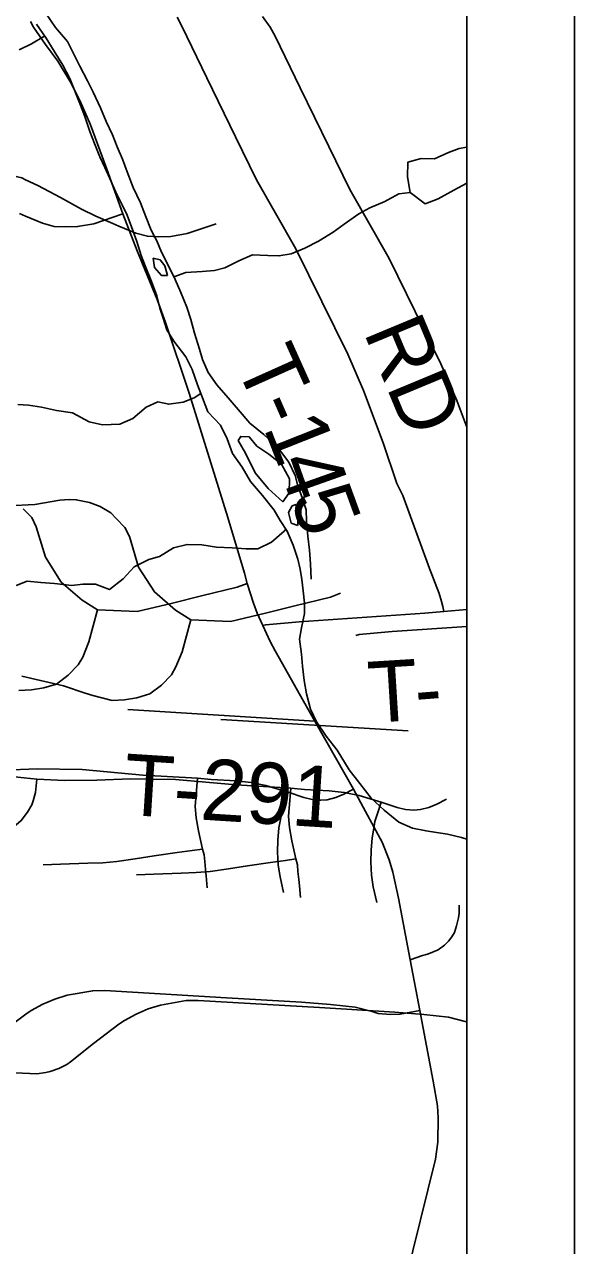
# Model space of a CAD drawing. Extents: x -38.2 to 41.9, y -4 to 24.9.
# Drawn here: x 8.49 to 9, y 18.257 to 19.391 of the extents above; entities that cross this region are included whole.
import ezdxf

# ---------------------------------------------------------------- set-up
doc = ezdxf.new("R2010")
doc.units = 0
for name, color, linetype in [('GM_X_Interchange_Ramps', 7, 'Continuous'), ('GM_X_Major_River', 7, 'Continuous'), ('GM_X_Minor_Lake', 7, 'Continuous'), ('GM_X_Minor_River', 7, 'Continuous'), ('GM_X_State_Location', 7, 'Continuous'), ('GM_X_State_Route', 7, 'Continuous'), ('GM_X_Township_Road', 7, 'Continuous'), ('GM_X_Township_Road_Text', 7, 'Continuous'), ('SH_Cut_Line', 7, 'Continuous'), ('SH_Data', 7, 'Continuous')]:
    doc.layers.add(name, color=color, linetype=linetype)

msp = doc.modelspace()

# ---------------------------------------------------------------- linework, layer by layer
at = {"layer": 'GM_X_Interchange_Ramps'}
for points in [[(5.6874, 16.3954), (5.9853, 16.3764), (6.413, 16.3602), (6.4263, 16.3595), (7.1336, 16.3198), (7.3442, 16.3107), (7.5793, 16.2961), (7.6901, 16.2894), (7.9696, 16.2752), (8.9, 16.2272), (8.9, 17.7063), (8.9, 17.9093), (8.9, 20.9), (5.1243, 20.9)], [(5.7739, 16.3862), (6.0718, 16.3672), (6.4995, 16.351), (6.5128, 16.3503), (7.2201, 16.3106), (7.4307, 16.3015), (7.6658, 16.2869), (7.7766, 16.2803), (8.0561, 16.266), (8.9, 16.2225), (8.9, 20.9), (5.2114, 20.9)]]:
    msp.add_lwpolyline(points, dxfattribs=at)
at = {"layer": 'GM_X_Major_River'}
for points in [[(8.7558, 18.8758), (8.7551, 18.8899), (8.754, 18.9028), (8.7526, 18.9157), (8.7512, 18.9297), (8.7509, 18.9403), (8.7475, 18.9506), (8.7434, 18.9624), (8.7408, 18.9719), (8.7349, 18.9844), (8.7243, 18.9982), (8.7119, 19.01), (8.6988, 19.0207), (8.6879, 19.0333), (8.6788, 19.044), (8.6683, 19.0562), (8.6601, 19.0676), (8.6548, 19.0798), (8.6522, 19.0893), (8.6474, 19.1041), (8.6441, 19.1167), (8.6404, 19.1284), (8.6348, 19.1418), (8.6296, 19.1539), (8.6247, 19.1642), (8.6168, 19.1794), (8.6124, 19.1897), (8.6071, 19.1996), (8.6019, 19.2129), (8.5974, 19.2251), (8.5907, 19.2395), (8.5851, 19.254), (8.5807, 19.2658), (8.5758, 19.2772), (8.5713, 19.2882), (8.5654, 19.3007), (8.5601, 19.3133), (8.5534, 19.3277), (8.5482, 19.3384), (8.5411, 19.3521), (8.5362, 19.362), (8.5295, 19.3749), (8.5186, 19.3879), (8.5092, 19.4016)], [(8.5008, 19.391), (8.5098, 19.3781), (8.5173, 19.3659), (8.5252, 19.353), (8.5319, 19.3404), (8.5375, 19.3267), (8.5416, 19.3157), (8.5457, 19.3054), (8.5502, 19.2914), (8.5546, 19.2803), (8.5595, 19.2678), (8.5643, 19.2579), (8.5688, 19.2476), (8.5744, 19.2351), (8.5804, 19.2233), (8.5849, 19.2138), (8.589, 19.2027), (8.5938, 19.1891), (8.5979, 19.1761), (8.6016, 19.1666), (8.6076, 19.1522), (8.6124, 19.1389), (8.6154, 19.1275), (8.6184, 19.118), (8.6217, 19.1073), (8.6284, 19.0967), (8.6393, 19.0822), (8.6453, 19.0704), (8.6501, 19.0563), (8.655, 19.0441), (8.6598, 19.0312)], [(8.6092, 19.1738), (8.6103, 19.1651), (8.6167, 19.1578), (8.6224, 19.1578)], [(8.6224, 19.1578), (8.6198, 19.1665), (8.6157, 19.1722), (8.6092, 19.1738)], [(8.6598, 19.0312), (8.6715, 19.0186), (8.6778, 19.0061), (8.6827, 18.9924), (8.6917, 18.9798), (8.6995, 18.9665), (8.7104, 18.9535), (8.7213, 18.9398), (8.727, 18.9303), (8.7333, 18.9204), (8.7389, 18.9074), (8.7434, 18.8945), (8.7456, 18.885), (8.7471, 18.8755), (8.7481, 18.8649), (8.7496, 18.8535), (8.7495, 18.844), (8.7468, 18.8307), (8.7448, 18.8201), (8.7466, 18.8061), (8.7477, 18.7951), (8.7491, 18.7818), (8.7513, 18.7693), (8.755, 18.7552), (8.7606, 18.7434), (8.7696, 18.7301), (8.7798, 18.7171), (8.791, 18.6988), (8.8008, 18.6862), (8.8113, 18.6725), (8.8233, 18.6614), (8.8369, 18.6503), (8.8497, 18.6446), (8.8622, 18.6422), (8.872, 18.6406), (8.8822, 18.639), (8.8951, 18.6359), (8.9, 18.6344)], [(8.7354, 18.956), (8.7355, 18.9689), (8.728, 18.9826), (8.7164, 18.9918), (8.7054, 18.9994), (8.6983, 19.0078), (8.6903, 19.0083), (8.6881, 19.0045)], [(8.6881, 19.0045), (8.6948, 18.9927), (8.7038, 18.9744), (8.7158, 18.9599), (8.7293, 18.9477), (8.7354, 18.956)], [(8.738, 18.9438), (8.7346, 18.9378), (8.7372, 18.9279), (8.7432, 18.9256)], [(8.7432, 18.9256), (8.7432, 18.9328), (8.7414, 18.945), (8.738, 18.9438)]]:
    msp.add_lwpolyline(points, dxfattribs=at)
at = {"layer": 'GM_X_Minor_Lake'}
for points in [[(8.9, 19.2769), (8.8929, 19.2755), (8.8831, 19.2717), (8.8702, 19.2661), (8.8577, 19.2664), (8.8452, 19.263)], [(8.8452, 19.263), (8.8449, 19.2492), (8.8475, 19.2346), (8.8615, 19.2243), (8.8736, 19.2289), (8.888, 19.2369), (8.9, 19.2434)]]:
    msp.add_lwpolyline(points, dxfattribs=at)
at = {"layer": 'GM_X_Minor_River'}
for points in [[(8.5084, 19.3801), (8.5076, 19.3795), (8.4962, 19.3727), (8.4849, 19.367)], [(8.6284, 19.1564), (8.6394, 19.1603), (8.6545, 19.1614), (8.6659, 19.1622), (8.6757, 19.1648), (8.6886, 19.1713), (8.7011, 19.177), (8.7154, 19.1762), (8.7257, 19.1758), (8.737, 19.1777), (8.7499, 19.183), (8.7624, 19.1895), (8.776, 19.1978), (8.7862, 19.2054), (8.7998, 19.2149), (8.81, 19.2206), (8.824, 19.2262), (8.8369, 19.2334), (8.8475, 19.2346), (8.8615, 19.2243), (8.8736, 19.2289), (8.888, 19.2369), (8.9, 19.2434)], [(8.6534, 19.0481), (8.647, 19.0442), (8.6368, 19.04), (8.6235, 19.0382), (8.6133, 19.0404), (8.6027, 19.0355), (8.5902, 19.0249), (8.5781, 19.0196), (8.5622, 19.0192), (8.5497, 19.0219), (8.5342, 19.0302), (8.5195, 19.0325), (8.5055, 19.0355), (8.4934, 19.0374), (8.4835, 19.0378)], [(8.7322, 18.9221), (8.7307, 18.9205), (8.719, 18.9103), (8.7061, 18.9039), (8.6955, 18.9039), (8.6823, 18.905), (8.6679, 18.9054), (8.6542, 18.9077), (8.6406, 18.908), (8.6281, 18.905), (8.6149, 18.897), (8.6051, 18.894), (8.5914, 18.8872), (8.5812, 18.8762), (8.5687, 18.8663), (8.5555, 18.8713), (8.5438, 18.8713), (8.5335, 18.8698), (8.5176, 18.8717), (8.5048, 18.8728), (8.4923, 18.8739), (8.4821, 18.8698)]]:
    msp.add_lwpolyline(points, dxfattribs=at)
at = {"layer": 'GM_X_State_Location'}
msp.add_line((8.672, 18.7455), (8.8456, 18.7349), dxfattribs=at)
for points in [[(8.9, 19.017), (8.8907, 19.0416), (8.8761, 19.0756), (8.8279, 19.1733), (8.7916, 19.2375), (8.7719, 19.2773), (8.7454, 19.332), (8.7222, 19.3798), (8.7177, 19.3883), (8.7104, 19.398)], [(8.4417, 19.2523), (8.4465, 19.2526), (8.458, 19.2526), (8.468, 19.2522), (8.4781, 19.2506), (8.4872, 19.2482), (8.4908, 19.2465)], [(8.4908, 19.2465), (8.5022, 19.2411), (8.5232, 19.2301), (8.5425, 19.2193), (8.5559, 19.2128), (8.5716, 19.206)], [(8.5716, 19.206), (8.5772, 19.2036), (8.593, 19.1971), (8.6037, 19.1941), (8.6141, 19.1936), (8.6254, 19.1939), (8.6405, 19.1965), (8.6676, 19.2057)], [(8.475, 18.9439), (8.4993, 18.9452), (8.5226, 18.9492), (8.5311, 18.9499), (8.5378, 18.9496), (8.5499, 18.9469), (8.5598, 18.9434), (8.5697, 18.9375), (8.575, 18.9319), (8.5829, 18.9237), (8.5871, 18.9153), (8.5956, 18.8871), (8.6102, 18.864), (8.6297, 18.8471), (8.644, 18.8382), (8.6807, 18.8366), (8.7133, 18.8444), (8.7404, 18.851), (8.7736, 18.8592), (8.7828, 18.8627)], [(8.4873, 18.7857), (8.5259, 18.7767), (8.5459, 18.77), (8.5531, 18.7678), (8.5711, 18.7633), (8.5826, 18.7639), (8.594, 18.7658), (8.606, 18.7693), (8.6167, 18.7774), (8.626, 18.787), (8.6302, 18.7943), (8.6359, 18.8084), (8.644, 18.8382)], [(8.7971, 18.8235), (8.8001, 18.8243), (8.8309, 18.8271), (8.9, 18.8319)], [(8.8812, 18.6717), (8.8723, 18.667), (8.8649, 18.6639), (8.857, 18.6619), (8.851, 18.6614), (8.8471, 18.6616), (8.8432, 18.6621), (8.8355, 18.6639), (8.8207, 18.6689), (8.8002, 18.675), (8.7864, 18.6778), (8.7725, 18.6794), (8.7494, 18.6807), (8.7367, 18.6819), (8.6861, 18.6848), (8.6297, 18.6899), (8.588, 18.6906), (8.5569, 18.6892), (8.527, 18.689), (8.5013, 18.6903), (8.4657, 18.694)], [(8.5013, 18.6903), (8.4998, 18.6778), (8.4978, 18.6701), (8.4964, 18.6664), (8.4926, 18.6595), (8.4867, 18.6518), (8.4821, 18.6479), (8.4725, 18.641), (8.4594, 18.6333), (8.4437, 18.6237), (8.4285, 18.6149), (8.4197, 18.6115), (8.4105, 18.6092), (8.4058, 18.6085), (8.3964, 18.608), (8.3897, 18.6084), (8.3815, 18.6099), (8.3735, 18.6125), (8.3616, 18.6192), (8.3486, 18.6286), (8.3432, 18.6346), (8.3326, 18.6473)], [(8.7457, 18.5802), (8.7447, 18.5911), (8.7441, 18.5972), (8.7434, 18.6044), (8.7429, 18.6107), (8.7415, 18.6161), (8.7376, 18.633), (8.7355, 18.6452), (8.7346, 18.6555), (8.7367, 18.6819)], [(8.8166, 18.5758), (8.8133, 18.5903), (8.8117, 18.6012), (8.8109, 18.6134), (8.8112, 18.6244), (8.8123, 18.6358), (8.8142, 18.6465), (8.8147, 18.651), (8.8171, 18.6582), (8.8207, 18.6689)], [(8.5936, 18.6014), (8.6096, 18.602), (8.635, 18.6029), (8.649, 18.6034), (8.6619, 18.6045), (8.679, 18.6069), (8.6966, 18.6097), (8.7179, 18.6129), (8.7319, 18.6148), (8.7415, 18.6161)], [(8.4813, 18.4177), (8.5012, 18.4168), (8.5095, 18.4178), (8.5135, 18.4188), (8.5215, 18.4215), (8.5289, 18.4253), (8.5324, 18.4277), (8.5538, 18.4448), (8.5773, 18.4629), (8.5825, 18.4662), (8.5932, 18.4721), (8.6045, 18.4769), (8.6158, 18.4805), (8.6396, 18.4846), (8.6507, 18.4848), (8.7635, 18.4781), (8.8333, 18.4739), (8.8601, 18.4718), (8.8831, 18.4692), (8.8986, 18.4652), (8.9, 18.4648)]]:
    msp.add_lwpolyline(points, dxfattribs=at)
at = {"layer": 'GM_X_State_Route'}
msp.add_lwpolyline([(8.843, 18.2237), (8.8711, 18.3374), (8.8733, 18.3532), (8.8736, 18.3759), (8.8728, 18.387), (8.8687, 18.41), (8.8564, 18.4755), (8.8476, 18.5224), (8.8367, 18.5798), (8.8315, 18.6039), (8.828, 18.6154), (8.8216, 18.6316), (8.8061, 18.6603), (8.7948, 18.6809), (8.7873, 18.6945), (8.7592, 18.7441), (8.7486, 18.7625), (8.7222, 18.8093), (8.7177, 18.8179), (8.7107, 18.8327), (8.7057, 18.8444), (8.7023, 18.8535), (8.6963, 18.8719), (8.6937, 18.8813), (8.6785, 18.9329), (8.6425, 19.0485), (8.6206, 19.1139), (8.6127, 19.1354), (8.5942, 19.1806), (8.5811, 19.2148), (8.566, 19.2565), (8.5509, 19.2974), (8.5413, 19.3195), (8.5324, 19.3372), (8.5206, 19.3566), (8.5093, 19.3722), (8.4982, 19.3883), (8.4954, 19.3933)], dxfattribs=at)
at = {"layer": 'GM_X_Township_Road'}
msp.add_line((8.5855, 18.7547), (8.7592, 18.7441), dxfattribs=at)
for points in [[(8.8786, 18.8457), (8.8778, 18.8504), (8.8767, 18.8551), (8.8744, 18.8624), (8.8653, 18.8857), (8.8407, 18.9534), (8.835, 18.9647), (8.8225, 19.0024), (8.8042, 19.0508), (8.7896, 19.0848), (8.7414, 19.1825), (8.7051, 19.2466), (8.6854, 19.2865), (8.659, 19.3412), (8.6358, 19.389), (8.6313, 19.3975)], [(8.4851, 19.2152), (8.4907, 19.2128), (8.5065, 19.2063), (8.5172, 19.2033), (8.5276, 19.2028), (8.539, 19.2031), (8.554, 19.2057), (8.5811, 19.2148)], [(8.4885, 18.9411), (8.4964, 18.9329), (8.5007, 18.9244), (8.5091, 18.8963), (8.5238, 18.8731), (8.5432, 18.8562), (8.5575, 18.8474), (8.5942, 18.8458), (8.6269, 18.8536), (8.6539, 18.8602), (8.6871, 18.8684), (8.6963, 18.8719)], [(8.4846, 18.7725), (8.4961, 18.7731), (8.5076, 18.775), (8.5195, 18.7784), (8.5302, 18.7866), (8.5395, 18.7962), (8.5438, 18.8035), (8.5494, 18.8176), (8.5575, 18.8474)], [(8.7107, 18.8327), (8.7136, 18.8335), (8.7444, 18.8363), (8.861, 18.8443), (8.8786, 18.8457), (8.9, 18.8478)], [(8.7948, 18.6809), (8.7859, 18.6762), (8.7784, 18.6731), (8.7705, 18.6711), (8.7646, 18.6706), (8.7606, 18.6708), (8.7567, 18.6713), (8.749, 18.6731), (8.7343, 18.6781), (8.7137, 18.6842), (8.6999, 18.687), (8.686, 18.6886), (8.6629, 18.6899), (8.6503, 18.6911), (8.5996, 18.694), (8.5432, 18.6991), (8.5015, 18.6998), (8.4704, 18.6984)], [(8.6592, 18.5894), (8.6582, 18.6003), (8.6576, 18.6064), (8.657, 18.6136), (8.6564, 18.6199), (8.655, 18.6253), (8.6511, 18.6422), (8.649, 18.6544), (8.6482, 18.6647), (8.6503, 18.6911)], [(8.7301, 18.585), (8.7268, 18.5995), (8.7252, 18.6104), (8.7245, 18.6226), (8.7247, 18.6336), (8.7258, 18.645), (8.7277, 18.6557), (8.7282, 18.6602), (8.7306, 18.6674), (8.7343, 18.6781)], [(8.5071, 18.6106), (8.5231, 18.6112), (8.5485, 18.6121), (8.5625, 18.6126), (8.5754, 18.6137), (8.5925, 18.6161), (8.6101, 18.6189), (8.6314, 18.6221), (8.6454, 18.624), (8.655, 18.6253)], [(8.8476, 18.5224), (8.8588, 18.5264), (8.8614, 18.5271), (8.8646, 18.5282), (8.8736, 18.5319), (8.8792, 18.536), (8.8832, 18.5398), (8.8863, 18.5438), (8.8885, 18.5478), (8.8906, 18.5539), (8.8923, 18.5614), (8.8929, 18.5658), (8.893, 18.5733)], [(8.4673, 18.454), (8.4909, 18.4721), (8.496, 18.4754), (8.5068, 18.4813), (8.518, 18.4861), (8.5293, 18.4897), (8.5531, 18.4938), (8.5642, 18.494), (8.677, 18.4873), (8.7468, 18.4831), (8.7736, 18.481), (8.7966, 18.4784), (8.8121, 18.4744), (8.8179, 18.4726), (8.8294, 18.4717), (8.8383, 18.4722), (8.8564, 18.4755)]]:
    msp.add_lwpolyline(points, dxfattribs=at)
at = {"layer": 'SH_Cut_Line'}
msp.add_lwpolyline([(5.6874, 16.3954), (5.9853, 16.3764), (6.413, 16.3602), (6.4263, 16.3595), (7.1336, 16.3198), (7.3442, 16.3107), (7.5793, 16.2961), (7.6901, 16.2894), (7.9696, 16.2752), (8.9, 16.2272), (8.9, 17.7063), (8.9, 17.9093), (8.9, 20.9), (2.1103, 20.9)], dxfattribs=at)
at = {"layer": 'SH_Data'}
for p, q in [((9, 21), (9, 14)), ((8.9, 20.9), (8.9, 17.9093))]:
    msp.add_line(p, q, dxfattribs=at)

# ---------------------------------------------------------------- texts
at = {"layer": 'GM_X_Township_Road_Text'}
for s, height, rotation, p in [('RD', 0.05682, 292.6176, (8.8039, 19.1054)), ('T', 0.0568, 294.1801, (8.6846, 19.0762)), ('-', 0.0568, 293.6035, (8.7019, 19.0376)), ('1', 0.0568, 291.6226, (8.7111, 19.0167)), ('4', 0.0568, 289.5327, (8.7238, 18.9846)), ('5', 0.0568, 290.0282, (8.7357, 18.9512)), ('T', 0.0568, 3.5421, (8.81, 18.7423)), ('-', 0.0568, 4.5139, (8.8535, 18.745)), ('T-291', 0.05682, 356.3536, (8.5804, 18.6573))]:
    msp.add_text(s, height=height, rotation=rotation, dxfattribs=at).set_placement(p)

doc.saveas('drawing.dxf')
